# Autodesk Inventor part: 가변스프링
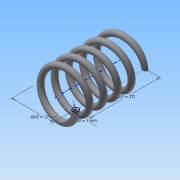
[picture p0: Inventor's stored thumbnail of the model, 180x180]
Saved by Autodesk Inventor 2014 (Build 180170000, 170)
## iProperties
Created: 2015-09
Part Number: 가변스프링
Material: 강철, 탄소
Document SubType Name: Modeling
Designer: study
Density: 1 g/cm^3
Appearance: 반연마
Mass: 2.40066 g
Surface Area: 32.5308 cm^2
Volume: 2.40066 cm^3
Author: study
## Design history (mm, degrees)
sketch "스케치1"
  geometry: L1 (0, 0)-(11, 0); L2 (11, 0)-(11, 37); L3 (11, 37)-(0, 37); L4 (0, 37)-(0, 0); C1 r 1.5 at (11, 0)
  constraints: 8 end point, 2 parallel, 1 centre point, 1 coincident, 1 horizontal, 1 perpendicular
  dimensions: "d0" = 3 diameter of C1; "d2" = 22 diameter of L2 L4; "d3" = 37 distance of L1.end L2.end (derived)
feature "코일1" sketch "스케치1" pitch "d4" = 10; turns "d6" = 5; dims "d5" = 37 (= d3), "d7" = 0, angle "d8" = 90 deg, angle "d9" = 90 deg, "d10" = 0, "d11" = 0
node "작업 평면1"
sketch "스케치2"
  geometry: L1 (-12.5, 0)-(-9.5, 0) reference; 1 further point
  constraints: 1 horizontal alignment
extrude "돌출1" cut sketch "스케치2" stored distance "d13" = 10; taper "d14" = 0 deg
node "작업 평면2"
sketch "스케치3"
  geometry: L1 (-9.5, 0)-(-12.5, 0) reference; 1 further point
  constraints: 1 horizontal alignment
extrude "돌출2" cut sketch "스케치3" stored distance "d16" = 10; taper "d17" = 0 deg
node "솔리드1"
node "절단 모서리 투영1"
node "절단 모서리 투영2"
other parameters: "d12" = 0, "d15" = 37 (= d3)
